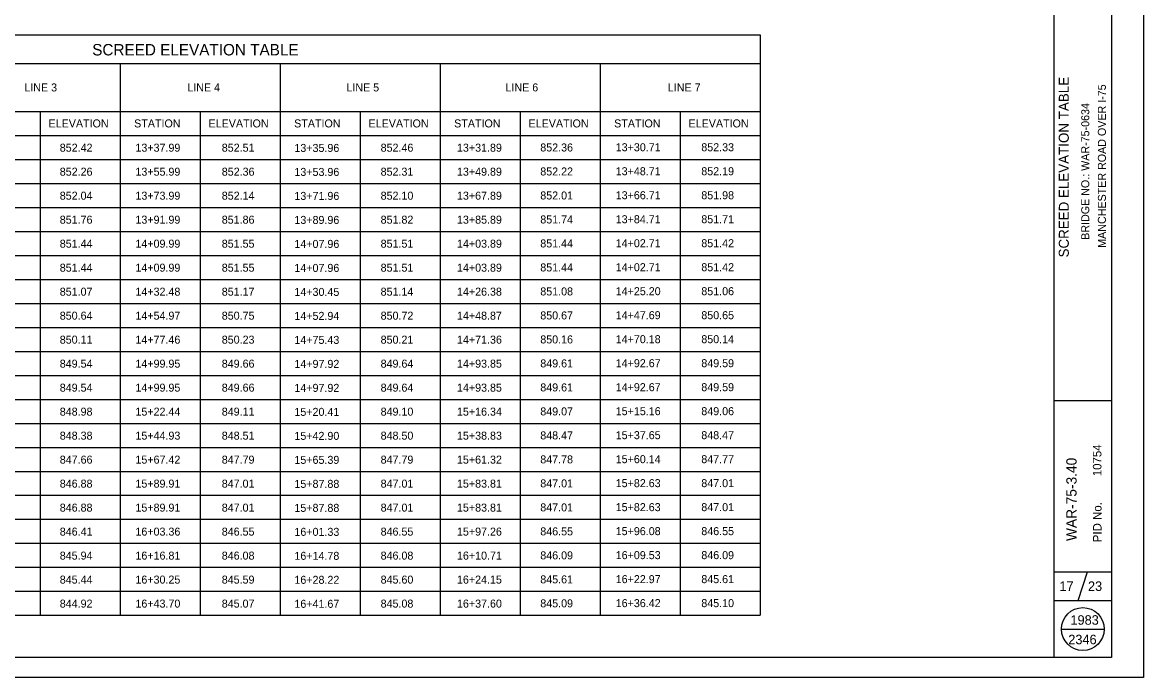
# Model space of a CAD drawing. Extents: x 1466871.1 to 1466907, y 570850.5 to 570872.5.
# Drawn here: x 1466886.76 to 1466906.38, y 570850.61 to 570862.08 of the extents above; entities that cross this region are included whole.
import ezdxf

# ---------------------------------------------------------------- set-up
doc = ezdxf.new("R2010")
doc.units = 0
for name, color, linetype in [('BR_P_Gen_Text', 7, 'Continuous'), ('Default', 7, 'Continuous'), ('SH_Border', 7, 'Continuous'), ('SH_Cut_Line', 7, 'Continuous'), ('SH_Data', 7, 'Continuous')]:
    doc.layers.add(name, color=color, linetype=linetype)

msp = doc.modelspace()

# ---------------------------------------------------------------- linework, layer by layer
at = {"layer": 'Default'}
for p, q in [((1466877.978, 570861.863), (1466899.667, 570861.863)), ((1466899.667, 570861.863), (1466899.667, 570853.804)), ((1466877.978, 570861.364), (1466899.667, 570861.364)), ((1466888.467, 570861.364), (1466888.467, 570851.704)), ((1466891.267, 570861.364), (1466891.267, 570851.704)), ((1466894.067, 570861.364), (1466894.067, 570851.704)), ((1466896.867, 570861.364), (1466896.867, 570851.704)), ((1466899.667, 570861.364), (1466899.667, 570851.704)), ((1466899.667, 570861.364), (1466899.667, 570853.804)), ((1466880.067, 570860.524), (1466899.667, 570860.524)), ((1466887.067, 570860.524), (1466887.067, 570851.704)), ((1466889.867, 570860.524), (1466889.867, 570851.704)), ((1466892.667, 570860.524), (1466892.667, 570851.704)), ((1466895.467, 570860.524), (1466895.467, 570851.704)), ((1466898.267, 570860.524), (1466898.267, 570851.704)), ((1466877.978, 570860.104), (1466899.667, 570860.104)), ((1466878.538, 570859.684), (1466899.667, 570859.684)), ((1466878.538, 570859.264), (1466899.667, 570859.264)), ((1466878.538, 570858.844), (1466899.667, 570858.844)), ((1466878.538, 570858.424), (1466899.667, 570858.424)), ((1466877.978, 570858.004), (1466899.667, 570858.004)), ((1466878.538, 570857.584), (1466899.667, 570857.584)), ((1466878.538, 570857.164), (1466899.667, 570857.164)), ((1466878.538, 570856.744), (1466899.667, 570856.744)), ((1466878.538, 570856.324), (1466899.667, 570856.324)), ((1466877.978, 570855.904), (1466899.667, 570855.904)), ((1466878.538, 570855.484), (1466899.667, 570855.484)), ((1466878.538, 570855.484), (1466899.667, 570855.484)), ((1466878.538, 570855.064), (1466899.667, 570855.064)), ((1466878.538, 570855.064), (1466899.667, 570855.064)), ((1466878.538, 570854.644), (1466899.667, 570854.644)), ((1466878.538, 570854.644), (1466899.667, 570854.644)), ((1466878.538, 570854.224), (1466899.667, 570854.224)), ((1466877.978, 570853.804), (1466899.667, 570853.804)), ((1466877.978, 570853.804), (1466899.667, 570853.804)), ((1466878.538, 570853.384), (1466899.667, 570853.384)), ((1466878.538, 570853.384), (1466899.667, 570853.384)), ((1466878.538, 570852.964), (1466899.667, 570852.964)), ((1466878.538, 570852.964), (1466899.667, 570852.964)), ((1466878.538, 570852.544), (1466899.667, 570852.544)), ((1466878.538, 570852.544), (1466899.667, 570852.544)), ((1466878.538, 570852.124), (1466899.667, 570852.124)), ((1466877.978, 570851.704), (1466899.667, 570851.704))]:
    msp.add_line(p, q, dxfattribs=at)
at = {"layer": 'SH_Border'}
for p, q in [((1466904.814, 570850.964), (1466904.814, 570871.964)), ((1466904.814, 570855.464), (1466905.814, 570855.464)), ((1466904.814, 570852.464), (1466905.814, 570852.464)), ((1466905.231, 570851.964), (1466905.397, 570852.464)), ((1466904.814, 570851.964), (1466905.814, 570851.964))]:
    msp.add_line(p, q, dxfattribs=at)
msp.add_lwpolyline([(1466874.314, 570871.964), (1466905.814, 570871.964), (1466905.814, 570850.964), (1466874.314, 570850.964)], close=True, dxfattribs=at)
at = {"layer": 'SH_Cut_Line'}
msp.add_lwpolyline([(1466906.376, 570850.614), (1466872.376, 570850.614), (1466872.376, 570872.264), (1466906.376, 570872.264)], close=True, dxfattribs=at)
at = {"layer": 'SH_Data'}
msp.add_line((1466904.939, 570851.464), (1466905.689, 570851.464), dxfattribs=at)
msp.add_circle((1466905.314, 570851.464), 0.375, dxfattribs=at)

# ---------------------------------------------------------------- texts
at = {"layer": 'BR_P_Gen_Text'}
for s, height, p in [('SCREED ELEVATION TABLE', 0.2, (1466887.978, 570861.504)), ('LINE 3', 0.14, (1466886.79, 570860.874)), ('LINE 4', 0.14, (1466889.642, 570860.874)), ('LINE 5', 0.14, (1466892.426, 570860.874)), ('LINE 6', 0.14, (1466895.211, 570860.874)), ('LINE 7', 0.14, (1466898.052, 570860.874)), ('ELEVATION', 0.14, (1466887.214, 570860.244)), ('STATION', 0.14, (1466888.712, 570860.244)), ('ELEVATION', 0.14, (1466890.014, 570860.244)), ('STATION', 0.14, (1466891.512, 570860.244)), ('ELEVATION', 0.14, (1466892.814, 570860.244)), ('STATION', 0.14, (1466894.312, 570860.244)), ('ELEVATION', 0.14, (1466895.614, 570860.244)), ('STATION', 0.14, (1466897.112, 570860.244)), ('ELEVATION', 0.14, (1466898.414, 570860.244)), ('852.42', 0.14, (1466887.41, 570859.819)), ('13+37.99', 0.14, (1466888.734, 570859.819)), ('852.51', 0.14, (1466890.245, 570859.819)), ('13+35.96', 0.14, (1466891.516, 570859.815)), ('852.46', 0.14, (1466893.025, 570859.819)), ('13+31.89', 0.14, (1466894.361, 570859.819)), ('852.36', 0.14, (1466895.819, 570859.823)), ('13+30.71', 0.14, (1466897.139, 570859.827)), ('852.33', 0.14, (1466898.637, 570859.827)), ('852.26', 0.14, (1466887.41, 570859.399)), ('13+55.99', 0.14, (1466888.734, 570859.399)), ('852.36', 0.14, (1466890.245, 570859.399)), ('13+53.96', 0.14, (1466891.516, 570859.395)), ('852.31', 0.14, (1466893.025, 570859.399)), ('13+49.89', 0.14, (1466894.361, 570859.399)), ('852.22', 0.14, (1466895.819, 570859.403)), ('13+48.71', 0.14, (1466897.139, 570859.407)), ('852.19', 0.14, (1466898.637, 570859.407)), ('852.04', 0.14, (1466887.41, 570858.979)), ('13+73.99', 0.14, (1466888.734, 570858.979)), ('852.14', 0.14, (1466890.245, 570858.979)), ('13+71.96', 0.14, (1466891.516, 570858.975)), ('852.10', 0.14, (1466893.025, 570858.979)), ('13+67.89', 0.14, (1466894.361, 570858.979)), ('852.01', 0.14, (1466895.819, 570858.983)), ('13+66.71', 0.14, (1466897.139, 570858.987)), ('851.98', 0.14, (1466898.637, 570858.987)), ('851.76', 0.14, (1466887.41, 570858.559)), ('13+91.99', 0.14, (1466888.734, 570858.559)), ('851.86', 0.14, (1466890.245, 570858.559)), ('13+89.96', 0.14, (1466891.516, 570858.555)), ('851.82', 0.14, (1466893.025, 570858.559)), ('13+85.89', 0.14, (1466894.361, 570858.559)), ('851.74', 0.14, (1466895.819, 570858.563)), ('13+84.71', 0.14, (1466897.139, 570858.567)), ('851.71', 0.14, (1466898.637, 570858.567)), ('851.44', 0.14, (1466887.41, 570858.139)), ('14+09.99', 0.14, (1466888.734, 570858.139)), ('851.55', 0.14, (1466890.245, 570858.139)), ('14+07.96', 0.14, (1466891.516, 570858.135)), ('851.51', 0.14, (1466893.025, 570858.139)), ('14+03.89', 0.14, (1466894.361, 570858.139)), ('851.44', 0.14, (1466895.819, 570858.143)), ('14+02.71', 0.14, (1466897.139, 570858.147)), ('851.42', 0.14, (1466898.637, 570858.147)), ('14+02.71', 0.14, (1466897.139, 570857.727)), ('851.42', 0.14, (1466898.637, 570857.727)), ('851.44', 0.14, (1466887.41, 570857.719)), ('14+09.99', 0.14, (1466888.734, 570857.719)), ('851.55', 0.14, (1466890.245, 570857.719)), ('14+07.96', 0.14, (1466891.516, 570857.715)), ('851.51', 0.14, (1466893.025, 570857.719)), ('14+03.89', 0.14, (1466894.361, 570857.719)), ('851.44', 0.14, (1466895.819, 570857.723)), ('851.07', 0.14, (1466887.41, 570857.299)), ('14+32.48', 0.14, (1466888.734, 570857.299)), ('851.17', 0.14, (1466890.245, 570857.299)), ('14+30.45', 0.14, (1466891.516, 570857.295)), ('851.14', 0.14, (1466893.025, 570857.299)), ('14+26.38', 0.14, (1466894.361, 570857.299)), ('851.08', 0.14, (1466895.819, 570857.303)), ('14+25.20', 0.14, (1466897.139, 570857.307)), ('851.06', 0.14, (1466898.637, 570857.307)), ('850.64', 0.14, (1466887.41, 570856.879)), ('14+54.97', 0.14, (1466888.734, 570856.879)), ('850.75', 0.14, (1466890.245, 570856.879)), ('14+52.94', 0.14, (1466891.516, 570856.875)), ('850.72', 0.14, (1466893.025, 570856.879)), ('14+48.87', 0.14, (1466894.361, 570856.879)), ('850.67', 0.14, (1466895.819, 570856.883)), ('14+47.69', 0.14, (1466897.139, 570856.887)), ('850.65', 0.14, (1466898.637, 570856.887)), ('850.11', 0.14, (1466887.41, 570856.459)), ('14+77.46', 0.14, (1466888.734, 570856.459)), ('850.23', 0.14, (1466890.245, 570856.459)), ('14+75.43', 0.14, (1466891.516, 570856.455)), ('850.21', 0.14, (1466893.025, 570856.459)), ('14+71.36', 0.14, (1466894.361, 570856.459)), ('850.16', 0.14, (1466895.819, 570856.463)), ('14+70.18', 0.14, (1466897.139, 570856.467)), ('850.14', 0.14, (1466898.637, 570856.467)), ('849.54', 0.14, (1466887.41, 570856.039)), ('14+99.95', 0.14, (1466888.734, 570856.039)), ('849.66', 0.14, (1466890.245, 570856.039)), ('14+97.92', 0.14, (1466891.516, 570856.035)), ('849.64', 0.14, (1466893.025, 570856.039)), ('14+93.85', 0.14, (1466894.361, 570856.039)), ('849.61', 0.14, (1466895.819, 570856.043)), ('14+92.67', 0.14, (1466897.139, 570856.047)), ('849.59', 0.14, (1466898.637, 570856.047)), ('849.54', 0.14, (1466887.41, 570855.619)), ('14+99.95', 0.14, (1466888.734, 570855.619)), ('849.66', 0.14, (1466890.245, 570855.619)), ('14+97.92', 0.14, (1466891.516, 570855.615)), ('849.64', 0.14, (1466893.025, 570855.619)), ('14+93.85', 0.14, (1466894.361, 570855.619)), ('849.61', 0.14, (1466895.819, 570855.623)), ('14+92.67', 0.14, (1466897.139, 570855.627)), ('849.59', 0.14, (1466898.637, 570855.627)), ('848.98', 0.14, (1466887.41, 570855.199)), ('15+22.44', 0.14, (1466888.734, 570855.199)), ('849.11', 0.14, (1466890.245, 570855.199)), ('15+20.41', 0.14, (1466891.516, 570855.195)), ('849.10', 0.14, (1466893.025, 570855.199)), ('15+16.34', 0.14, (1466894.361, 570855.199)), ('849.07', 0.14, (1466895.819, 570855.203)), ('15+15.16', 0.14, (1466897.139, 570855.207)), ('849.06', 0.14, (1466898.637, 570855.207)), ('848.47', 0.14, (1466895.819, 570854.783)), ('15+37.65', 0.14, (1466897.139, 570854.787)), ('848.47', 0.14, (1466898.637, 570854.787)), ('848.38', 0.14, (1466887.41, 570854.779)), ('15+44.93', 0.14, (1466888.734, 570854.779)), ('848.51', 0.14, (1466890.245, 570854.779)), ('15+42.90', 0.14, (1466891.516, 570854.775)), ('848.50', 0.14, (1466893.025, 570854.779)), ('15+38.83', 0.14, (1466894.361, 570854.779)), ('847.66', 0.14, (1466887.41, 570854.359)), ('15+67.42', 0.14, (1466888.734, 570854.359)), ('847.79', 0.14, (1466890.245, 570854.359)), ('15+65.39', 0.14, (1466891.516, 570854.355)), ('847.79', 0.14, (1466893.025, 570854.359)), ('15+61.32', 0.14, (1466894.361, 570854.359)), ('847.78', 0.14, (1466895.819, 570854.363)), ('15+60.14', 0.14, (1466897.139, 570854.367)), ('847.77', 0.14, (1466898.637, 570854.367)), ('846.88', 0.14, (1466887.41, 570853.939)), ('15+89.91', 0.14, (1466888.734, 570853.939)), ('847.01', 0.14, (1466890.245, 570853.939)), ('15+87.88', 0.14, (1466891.516, 570853.935)), ('847.01', 0.14, (1466893.025, 570853.939)), ('15+83.81', 0.14, (1466894.361, 570853.939)), ('847.01', 0.14, (1466895.819, 570853.943)), ('15+82.63', 0.14, (1466897.139, 570853.947)), ('847.01', 0.14, (1466898.637, 570853.947)), ('846.88', 0.14, (1466887.41, 570853.519)), ('15+89.91', 0.14, (1466888.734, 570853.519)), ('847.01', 0.14, (1466890.245, 570853.519)), ('15+87.88', 0.14, (1466891.516, 570853.515)), ('847.01', 0.14, (1466893.025, 570853.519)), ('15+83.81', 0.14, (1466894.361, 570853.519)), ('847.01', 0.14, (1466895.819, 570853.523)), ('15+82.63', 0.14, (1466897.139, 570853.527)), ('847.01', 0.14, (1466898.637, 570853.527)), ('846.41', 0.14, (1466887.41, 570853.099)), ('16+03.36', 0.14, (1466888.734, 570853.099)), ('846.55', 0.14, (1466890.245, 570853.099)), ('16+01.33', 0.14, (1466891.516, 570853.095)), ('846.55', 0.14, (1466893.025, 570853.099)), ('15+97.26', 0.14, (1466894.361, 570853.099)), ('846.55', 0.14, (1466895.819, 570853.103)), ('15+96.08', 0.14, (1466897.139, 570853.107)), ('846.55', 0.14, (1466898.637, 570853.107)), ('845.94', 0.14, (1466887.41, 570852.679)), ('16+16.81', 0.14, (1466888.734, 570852.679)), ('846.08', 0.14, (1466890.245, 570852.679)), ('16+14.78', 0.14, (1466891.516, 570852.675)), ('846.08', 0.14, (1466893.025, 570852.679)), ('16+10.71', 0.14, (1466894.361, 570852.679)), ('846.09', 0.14, (1466895.819, 570852.683)), ('16+09.53', 0.14, (1466897.139, 570852.687)), ('846.09', 0.14, (1466898.637, 570852.687)), ('845.44', 0.14, (1466887.41, 570852.259)), ('16+30.25', 0.14, (1466888.734, 570852.259)), ('845.59', 0.14, (1466890.245, 570852.259)), ('16+28.22', 0.14, (1466891.516, 570852.255)), ('845.60', 0.14, (1466893.025, 570852.259)), ('16+24.15', 0.14, (1466894.361, 570852.259)), ('845.61', 0.14, (1466895.819, 570852.263)), ('16+22.97', 0.14, (1466897.139, 570852.267)), ('845.61', 0.14, (1466898.637, 570852.267)), ('845.09', 0.14, (1466895.819, 570851.843)), ('16+36.42', 0.14, (1466897.139, 570851.847)), ('845.10', 0.14, (1466898.637, 570851.847)), ('844.92', 0.14, (1466887.41, 570851.839)), ('16+43.70', 0.14, (1466888.734, 570851.839)), ('845.07', 0.14, (1466890.245, 570851.839)), ('16+41.67', 0.14, (1466891.516, 570851.835)), ('845.08', 0.14, (1466893.025, 570851.839)), ('16+37.60', 0.14, (1466894.361, 570851.839))]:
    msp.add_text(s, height=height, dxfattribs=at).set_placement(p)
at = {"layer": 'SH_Data'}
for s, height, p in [('SCREED ELEVATION TABLE', 0.175, (1466905.068, 570857.968)), ('MANCHESTER ROAD OVER I-75', 0.14, (1466905.717, 570858.137)), ('BRIDGE NO.: WAR-75-0634', 0.14, (1466905.426, 570858.277)), (' 10754', 0.15, (1466905.639, 570854.082)), ('WAR-75-3.40', 0.18, (1466905.204, 570853.004)), ('PID No.', 0.15, (1466905.641, 570852.983))]:
    msp.add_text(s, height=height, rotation=90, dxfattribs=at).set_placement(p)
for s, p in [(' 17', (1466904.842, 570852.131)), (' 23', (1466905.342, 570852.131)), ('1983', (1466905.097, 570851.539)), ('2346', (1466905.059, 570851.197))]:
    msp.add_text(s, height=0.1666, dxfattribs=at).set_placement(p)

doc.saveas('drawing.dxf')
